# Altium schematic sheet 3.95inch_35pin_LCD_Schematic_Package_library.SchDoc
size A4; PageSetup: Record=PageOptions¦CenterHorizontal=True¦CenterVertical=True¦PrintScale=0.97¦XCorrection=1.00¦YCorrection=1.00¦PrintKind=0¦BorderSize=5000000¦LeftOffset=0¦BottomOffset=0¦Orientation=2¦PaperLength=1000¦PaperWidth=1000¦Scale=100¦PaperSource=7¦PrintQuality=-4¦MediaType=1¦DitherType=10¦PaperKind=A4¦PrintScaleMode=1
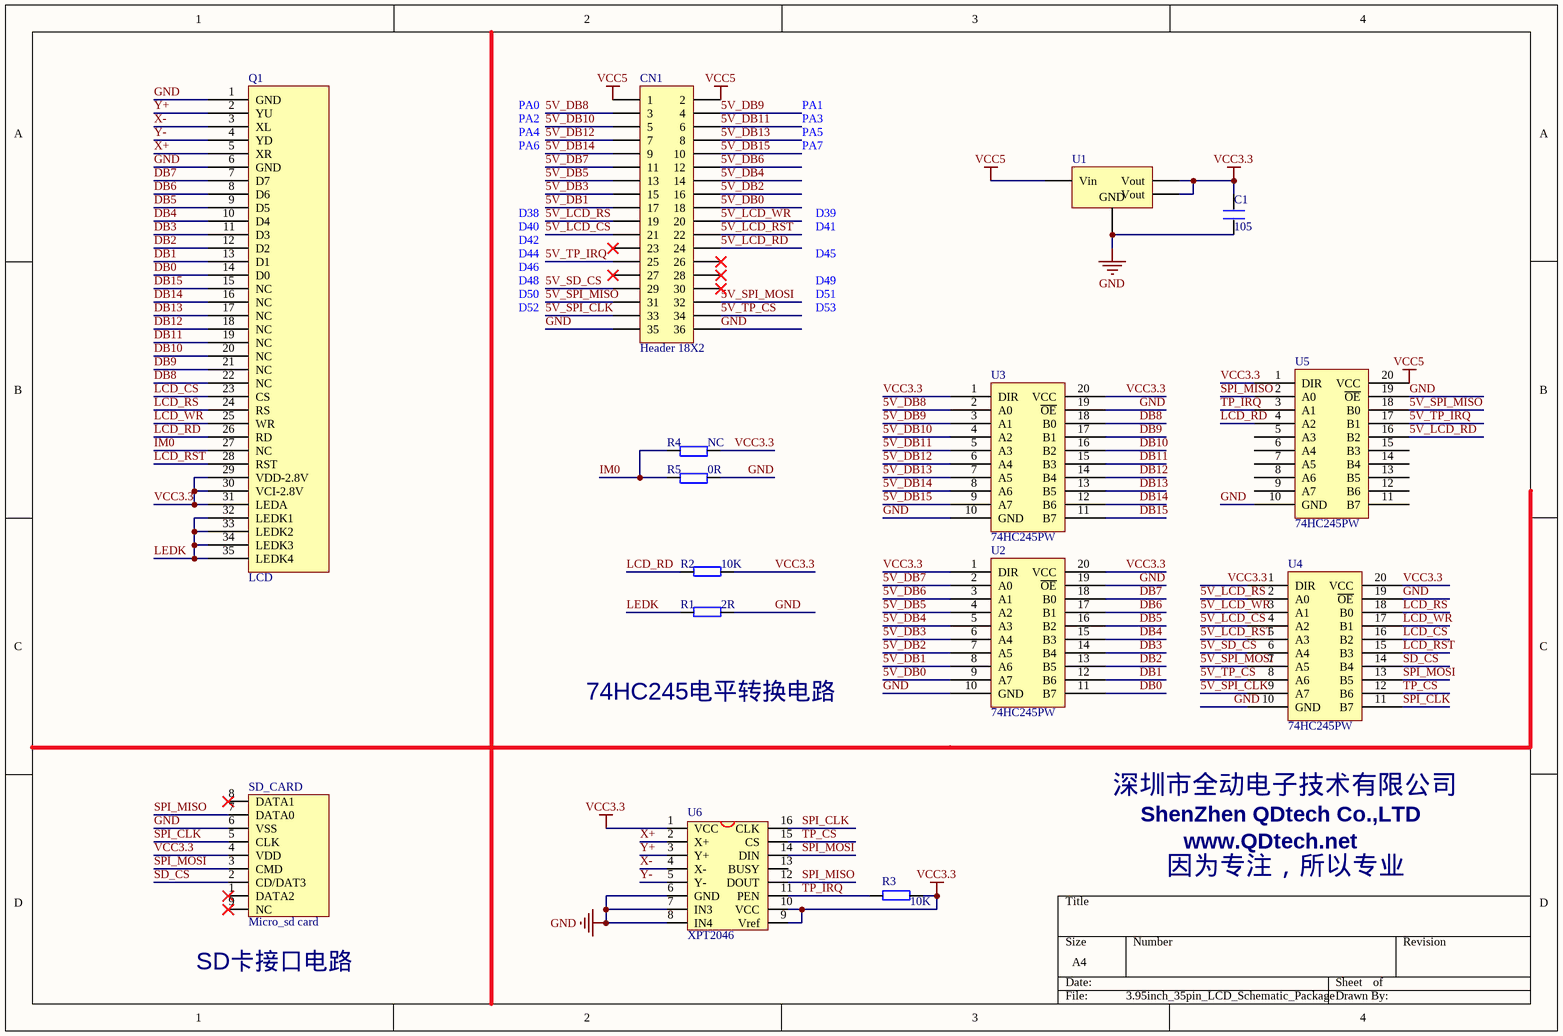
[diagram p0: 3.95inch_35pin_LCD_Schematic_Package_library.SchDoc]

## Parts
C1  105  [0805]
CN1  Header 18X2  [HDR2X18]
Q1  LCD  [DT40HV004]
R1  2R  [0805]
R2  10K  [0805]
R3  10K  [0805]
R4  NC  [0805]
R5  0R  [0805]
SD_CARD  Micro_sd card  [MicroTF]
U1  LM1117  [SOT223-4M]  (value not drawn)
U2  74HC245PW  [TSSOP20]
U3  74HC245PW  [TSSOP20]
U4  74HC245PW  [TSSOP20]
U5  74HC245PW  [TSSOP20]
U6  XPT2046  [SSOP16]

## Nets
GND: C1.2 CN1.35 CN1.36 Q1.1(GND) Q1.6(GND) R1.1 R5.2 SD_CARD.6(VSS) U1.1(GND) U2.10(GND) U2.19(~{OE}) U3.10(GND) U3.19(~{OE}) U4.10(GND) U4.19(~{OE}) U5.10(GND) U5.19(~{OE}) U6.6(GND) U6.7(IN3) U6.8(IN4)
VCC3.3: C1.1 Q1.29(VDD-2.8V) Q1.30(VCI-2.8V) Q1.31(LEDA) R2.1 R3.1 R4.2 SD_CARD.4(VDD) U1.2(Vout) U1.4(Vout) U2.1(DIR) U2.20(VCC) U3.1(DIR) U3.20(VCC) U4.1(DIR) U4.20(VCC) U5.1(DIR) U6.1(VCC) U6.9(Vref) U6.10(VCC)
VCC5: CN1.1 CN1.2 U1.3(Vin) U5.20(VCC)
5V_DB0: CN1.18 U2.9(A7)
5V_DB1: CN1.17 U2.8(A6)
5V_DB2: CN1.16 U2.7(A5)
5V_DB3: CN1.15 U2.6(A4)
5V_DB4: CN1.14 U2.5(A3)
5V_DB5: CN1.13 U2.4(A2)
5V_DB6: CN1.12 U2.3(A1)
5V_DB7: CN1.11 U2.2(A0)
5V_DB8: CN1.3 U3.2(A0)
5V_DB9: CN1.4 U3.3(A1)
5V_DB10: CN1.5 U3.4(A2)
5V_DB11: CN1.6 U3.5(A3)
5V_DB12: CN1.7 U3.6(A4)
5V_DB13: CN1.8 U3.7(A5)
5V_DB14: CN1.9 U3.8(A6)
5V_DB15: CN1.10 U3.9(A7)
5V_LCD_CS: CN1.21 U4.4(A2)
5V_LCD_RD: CN1.24 U5.16(B2)
5V_LCD_RS: CN1.19 U4.2(A0)
5V_LCD_RST: CN1.22 U4.5(A3)
5V_LCD_WR: CN1.20 U4.3(A1)
5V_SD_CS: CN1.29 U4.6(A4)
5V_SPI_CLK: CN1.33 U4.9(A7)
5V_SPI_MISO: CN1.31 U5.18(B0)
5V_SPI_MOSI: CN1.32 U4.7(A5)
5V_TP_CS: CN1.34 U4.8(A6)
5V_TP_IRQ: CN1.25 U5.17(B1)
DB0: Q1.14(D0) U2.11(B7)
DB1: Q1.13(D1) U2.12(B6)
DB2: Q1.12(D2) U2.13(B5)
DB3: Q1.11(D3) U2.14(B4)
DB4: Q1.10(D4) U2.15(B3)
DB5: Q1.9(D5) U2.16(B2)
DB6: Q1.8(D6) U2.17(B1)
DB7: Q1.7(D7) U2.18(B0)
DB8: Q1.22(NC) U3.18(B0)
DB9: Q1.21(NC) U3.17(B1)
DB10: Q1.20(NC) U3.16(B2)
DB11: Q1.19(NC) U3.15(B3)
DB12: Q1.18(NC) U3.14(B4)
DB13: Q1.17(NC) U3.13(B5)
DB14: Q1.16(NC) U3.12(B6)
DB15: Q1.15(NC) U3.11(B7)
IM0: Q1.27(NC) R4.1 R5.1
LCD_CS: Q1.23(CS) U4.16(B2)
LCD_RD: Q1.26(RD) R2.2 U5.4(A2)
LCD_RS: Q1.24(RS) U4.18(B0)
LCD_RST: Q1.28(RST) U4.15(B3)
LCD_WR: Q1.25(WR) U4.17(B1)
LEDK: Q1.32(LEDK1) Q1.33(LEDK2) Q1.34(LEDK3) Q1.35(LEDK4) R1.2
SD_CS: SD_CARD.2(CD/DAT3) U4.14(B4)
SPI_CLK: SD_CARD.5(CLK) U4.11(B7) U6.16(CLK)
SPI_MISO: SD_CARD.7(DATA0) U5.2(A0) U6.12(DOUT)
SPI_MOSI: SD_CARD.3(CMD) U4.13(B5) U6.14(DIN)
TP_CS: U4.12(B6) U6.15(CS)
TP_IRQ: R3.2 U5.3(A1) U6.11(PEN)
X+: Q1.5(XR) U6.2(X+)
X-: Q1.3(XL) U6.4(X-)
Y+: Q1.2(YU) U6.3(Y+)
Y-: Q1.4(YD) U6.5(Y-)

Not connected (* = marked no-connect by the designer): CN1 23* 26* 27* 28* 30*; SD_CARD 1(DATA2)* 8(DATA1)* 9(NC)*; U5 5(A3) 6(A4) 7(A5) 8(A6) 9(A7) 11(B7) 12(B6) 13(B5) 14(B4) 15(B3); U6 13(BUSY)

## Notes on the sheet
- PA0
- PA1
- PA2
- PA4
- PA6
- PA3
- PA5
- PA7
- D42
- D40
- D38
- D39
- D41
- D52
- D50
- D48
- D46
- D44
- D53
- D51
- D45
- D49
- 74HC245电平转换电路
- 深圳市全动电子技术有限公司
- ShenZhen QDtech Co.,LTD
- www.QDtech.net
- 因为专注，所以专业
- (near SD_CARD) SD卡接口电路

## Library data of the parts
C1 = C
CN1 = Header 18X2: Header, 18-Pin, Dual row
Q1 = DT40HV004-l1l3: 35pin LCD
R1-R5 = R
U1 = LM1117: Voltage Regulator
U2-U5 = 74HC245D
U6 = ADS7843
